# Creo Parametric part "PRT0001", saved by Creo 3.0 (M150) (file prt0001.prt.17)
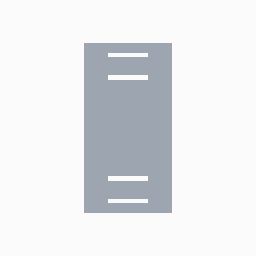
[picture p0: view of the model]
Units: millimeter Newton Second (mmNs); MM, TONNE, SECS

Created from: INLBS_PART_SOLID.PRT

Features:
  1. datum plane "RIGHT"
  2. datum plane "TOP"
  3. datum plane "FRONT"
  4. coordinate system
  5. sketch "Sketch 1"
  6. sketch "Sketch 2"
  7. extrusion "Extrude 1"
  8. extruded cut "Extrude 2"

Surfaces: 25 plane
